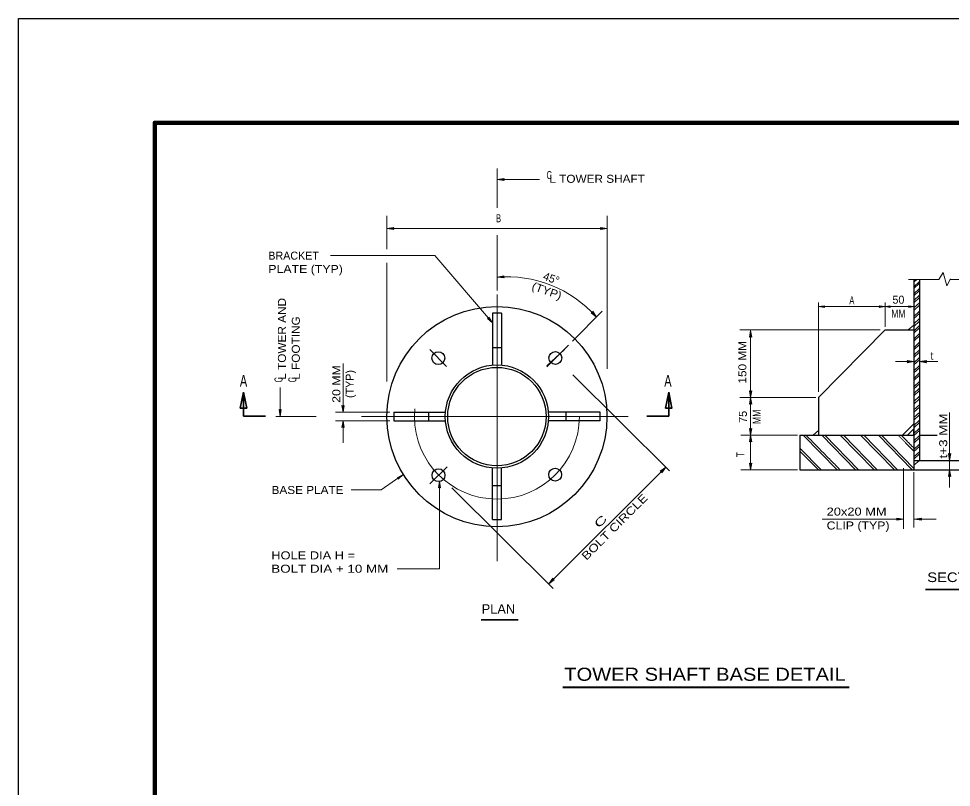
# Model space of a CAD drawing. Extents: x 312601.859 to 312602.7, y 144420.109 to 144420.704.
# Drawn here: x 312601.8593 to 312602.209, y 144420.4155 to 144420.7035 of the extents above; entities that cross this region are included whole.
import ezdxf
from ezdxf.enums import TextEntityAlignment as Align

# ---------------------------------------------------------------- set-up
doc = ezdxf.new("R2010")
doc.units = 0
doc.header["$LTSCALE"] = 0.0012
doc.linetypes.add('DOT_DASHED', pattern=[7.7, 5, -1.2, 0.3, -1.2])
doc.linetypes.add('LONG_DASHED', pattern=[7.5, 6, -1.5])
for name, color, linetype, lineweight in [('1', 7, 'Continuous', 13), ('2', 7, 'Continuous', 13), ('39', 7, 'Continuous', 13)]:
    doc.layers.add(name, color=color, linetype=linetype, lineweight=lineweight)

msp = doc.modelspace()

# ---------------------------------------------------------------- hatches: boundary and pattern name
at = {"layer": '39'}
for points in [[(312602.041, 144420.6432), (312602.0413, 144420.6428), (312602.0387, 144420.6432), (312602.0413, 144420.6436)], [(312601.9996, 144420.6249), (312601.9999, 144420.6245), (312601.9973, 144420.6249), (312601.9999, 144420.6253)], [(312602.0776, 144420.6249), (312602.0774, 144420.6253), (312602.0799, 144420.6249), (312602.0774, 144420.6245)], [(312602.041, 144420.6068), (312602.0413, 144420.6064), (312602.0387, 144420.6066), (312602.0412, 144420.6072)], [(312602.0743, 144420.5934), (312602.0745, 144420.5939), (312602.0759, 144420.5917), (312602.0739, 144420.5933)], [(312602.1612, 144420.5956), (312602.1614, 144420.5953), (312602.1592, 144420.5956), (312602.1614, 144420.5959)], [(312602.1821, 144420.5956), (312602.1819, 144420.5959), (312602.1841, 144420.5956), (312602.1819, 144420.5953)], [(312602.1858, 144420.5956), (312602.186, 144420.5953), (312602.1841, 144420.5956), (312602.186, 144420.5959)], [(312602.1932, 144420.5956), (312602.193, 144420.5959), (312602.1949, 144420.5956), (312602.193, 144420.5953)], [(312602.0354, 144420.5913), (312602.0355, 144420.5917), (312602.0369, 144420.5895), (312602.035, 144420.5912)], [(312602.1337, 144420.5843), (312602.1333, 144420.5841), (312602.1337, 144420.5866), (312602.1341, 144420.5841)], [(312602.1926, 144420.575), (312602.1924, 144420.5754), (312602.1949, 144420.575), (312602.1924, 144420.5746)], [(312602.1993, 144420.575), (312602.1996, 144420.5746), (312602.197, 144420.575), (312602.1996, 144420.5754)], [(312602.1337, 144420.5638), (312602.1341, 144420.5641), (312602.1337, 144420.5615), (312602.1333, 144420.5641)], [(312601.9809, 144420.5583), (312601.9813, 144420.5586), (312601.9809, 144420.556), (312601.9805, 144420.5586)], [(312602.1337, 144420.5592), (312602.1333, 144420.559), (312602.1337, 144420.5615), (312602.1341, 144420.559)], [(312601.9573, 144420.5567), (312601.9577, 144420.557), (312601.9573, 144420.5544), (312601.9569, 144420.557)], [(312601.9809, 144420.5505), (312601.9805, 144420.5503), (312601.9809, 144420.5528), (312601.9813, 144420.5503)], [(312602.1337, 144420.5497), (312602.1341, 144420.55), (312602.1337, 144420.5474), (312602.1333, 144420.55)], [(312602.1337, 144420.5451), (312602.1333, 144420.5449), (312602.1337, 144420.5474), (312602.1341, 144420.5449)], [(312602.2083, 144420.5403), (312602.2087, 144420.5406), (312602.2083, 144420.538), (312602.2079, 144420.5406)], [(312602.1003, 144420.5338), (312602.0998, 144420.5339), (312602.1019, 144420.5354), (312602.1004, 144420.5333)], [(312602.1337, 144420.5367), (312602.1341, 144420.537), (312602.1337, 144420.5344), (312602.1333, 144420.537)], [(312602.2083, 144420.5322), (312602.2079, 144420.532), (312602.2083, 144420.5345), (312602.2087, 144420.532)], [(312602.0016, 144420.5314), (312602.0012, 144420.5315), (312602.0035, 144420.5327), (312602.0016, 144420.5309)], [(312602.0171, 144420.5279), (312602.0167, 144420.5277), (312602.0171, 144420.5302), (312602.0175, 144420.5277)], [(312602.1887, 144420.516), (312602.1885, 144420.5164), (312602.191, 144420.516), (312602.1885, 144420.5156)], [(312602.1974, 144420.516), (312602.1977, 144420.5156), (312602.1951, 144420.516), (312602.1977, 144420.5164)], [(312602.0596, 144420.4933), (312602.0601, 144420.4932), (312602.058, 144420.4917), (312602.0595, 144420.4938)]]:
    msp.add_hatch(color=256, dxfattribs=at).paths.add_polyline_path(points)

# ---------------------------------------------------------------- linework, layer by layer
at = {"layer": '1'}
for p, q in [((312602.0387, 144420.6473), (312602.0387, 144420.6326)), ((312602.0387, 144420.6432), (312602.0545, 144420.6432)), ((312601.9973, 144420.6171), (312601.9973, 144420.6296)), ((312602.0799, 144420.5723), (312602.0799, 144420.6296)), ((312601.9973, 144420.6249), (312602.0799, 144420.6249)), ((312602.0387, 144420.6224), (312602.0387, 144420.6016)), ((312601.9762, 144420.6148), (312602.0153, 144420.6148)), ((312601.9973, 144420.5676), (312601.9973, 144420.612)), ((312602.1929, 144420.6058), (312602.2042, 144420.6058)), ((312602.1949, 144420.6048), (312602.196, 144420.6058)), ((312602.1949, 144420.6053), (312602.1954, 144420.6058)), ((312602.1949, 144420.603), (312602.197, 144420.605)), ((312602.1949, 144420.6024), (312602.197, 144420.6044)), ((312602.2085, 144420.6058), (312602.2239, 144420.6058)), ((312602.1949, 144420.6004), (312602.197, 144420.6024)), ((312602.1949, 144420.5997), (312602.197, 144420.6017)), ((312602.1592, 144420.5971), (312602.1592, 144420.5637)), ((312602.1841, 144420.588), (312602.1841, 144420.5971)), ((312602.1949, 144420.5979), (312602.197, 144420.5999)), ((312602.1949, 144420.597), (312602.197, 144420.599)), ((312602.1949, 144420.5951), (312602.197, 144420.597)), ((312602.1592, 144420.5956), (312602.1841, 144420.5956)), ((312602.1841, 144420.5956), (312602.1949, 144420.5956)), ((312602.1949, 144420.5942), (312602.197, 144420.5962)), ((312602.1949, 144420.5919), (312602.197, 144420.5939)), ((312602.1949, 144420.5911), (312602.197, 144420.593)), ((312602.1949, 144420.5891), (312602.197, 144420.5911)), ((312602.1949, 144420.5882), (312602.197, 144420.5902)), ((312602.1297, 144420.5869), (312602.1823, 144420.5869)), ((312602.1337, 144420.5615), (312602.1337, 144420.5866)), ((312602.1949, 144420.5864), (312602.197, 144420.5885)), ((312602.1949, 144420.5856), (312602.197, 144420.5876)), ((312602.1949, 144420.5834), (312602.197, 144420.5855)), ((312602.1949, 144420.5826), (312602.197, 144420.5846)), ((312602.0639, 144420.5796), (312602.0621, 144420.5778)), ((312602.1949, 144420.5794), (312602.197, 144420.5814)), ((312602.1949, 144420.5774), (312602.197, 144420.5794)), ((312602.197, 144420.5823), (312602.1951, 144420.5804)), ((312602.1949, 144420.5765), (312602.197, 144420.5785)), ((312602.1949, 144420.5746), (312602.197, 144420.5766)), ((312601.9809, 144420.5743), (312601.9809, 144420.556)), ((312602.188, 144420.575), (312602.1949, 144420.575)), ((312602.1949, 144420.5738), (312602.197, 144420.5757)), ((312602.1949, 144420.5716), (312602.197, 144420.5736)), ((312602.1949, 144420.5708), (312602.197, 144420.5727)), ((312602.197, 144420.575), (312602.2039, 144420.575)), ((312602.067, 144420.57), (312602.1033, 144420.5341)), ((312602.1949, 144420.5687), (312602.197, 144420.5708)), ((312602.1949, 144420.5679), (312602.197, 144420.5699)), ((312602.1949, 144420.5656), (312602.197, 144420.5676)), ((312602.1949, 144420.5648), (312602.197, 144420.5667)), ((312601.9573, 144420.5653), (312601.9573, 144420.5544)), ((312602.1949, 144420.563), (312602.197, 144420.565)), ((312602.1949, 144420.5622), (312602.197, 144420.5642)), ((312602.1949, 144420.56), (312602.197, 144420.562)), ((312602.1297, 144420.5615), (312602.1582, 144420.5615)), ((312602.1949, 144420.5591), (312602.197, 144420.5611)), ((312602.1949, 144420.5569), (312602.197, 144420.5588)), ((312601.9781, 144420.556), (312601.9985, 144420.556)), ((312602.1949, 144420.556), (312602.197, 144420.5579)), ((312602.1949, 144420.554), (312602.197, 144420.5559)), ((312602.1949, 144420.5531), (312602.197, 144420.5551)), ((312601.9708, 144420.5544), (312601.9557, 144420.5544)), ((312601.9781, 144420.5528), (312601.9985, 144420.5528)), ((312601.9809, 144420.5528), (312601.9809, 144420.5446)), ((312602.1949, 144420.5511), (312602.197, 144420.5531)), ((312602.1949, 144420.5502), (312602.197, 144420.5522)), ((312602.1947, 144420.5498), (312602.1947, 144420.5474)), ((312602.1949, 144420.5481), (312602.197, 144420.5501)), ((312602.1949, 144420.5473), (312602.197, 144420.5492)), ((312602.13, 144420.5474), (312602.1513, 144420.5474)), ((312602.1534, 144420.5474), (312602.1661, 144420.5345)), ((312602.1604, 144420.5474), (312602.173, 144420.5345)), ((312602.1615, 144420.5474), (312602.1742, 144420.5345)), ((312602.1673, 144420.5474), (312602.18, 144420.5345)), ((312602.1685, 144420.5474), (312602.1811, 144420.5345)), ((312602.1749, 144420.5474), (312602.1877, 144420.5345)), ((312602.1761, 144420.5474), (312602.1888, 144420.5345)), ((312602.1817, 144420.5474), (312602.1943, 144420.5345)), ((312602.1828, 144420.5474), (312602.1949, 144420.535)), ((312602.1949, 144420.5453), (312602.197, 144420.5473)), ((312602.1949, 144420.5444), (312602.197, 144420.5464)), ((312602.1522, 144420.5426), (312602.1602, 144420.5345)), ((312602.1522, 144420.5414), (312602.1591, 144420.5345)), ((312602.1949, 144420.5421), (312602.197, 144420.5441)), ((312602.1949, 144420.5413), (312602.197, 144420.5432)), ((312602.1949, 144420.5393), (312602.197, 144420.5412)), ((312602.1949, 144420.5384), (312602.197, 144420.5404)), ((312602.197, 144420.538), (312602.1949, 144420.5362)), ((312602.058, 144420.4917), (312602.1019, 144420.5354)), ((312602.13, 144420.5344), (312602.1513, 144420.5344)), ((312602.191, 144420.5123), (312602.191, 144420.5351)), ((312602.1949, 144420.5336), (312602.1949, 144420.5129)), ((312602.0171, 144420.5302), (312602.0171, 144420.4973)), ((312602.0217, 144420.5277), (312602.0597, 144420.49)), ((312601.9839, 144420.5269), (312601.9952, 144420.5269)), ((312602.1605, 144420.516), (312602.191, 144420.516)), ((312602.1951, 144420.516), (312602.2032, 144420.516)), ((312602.0171, 144420.4973), (312602.0012, 144420.4973))]:
    msp.add_line(p, q, dxfattribs=at)
at = {"layer": '1', "lineweight": 25}
for p, q in [((312602.1949, 144420.6058), (312602.1949, 144420.5345)), ((312602.197, 144420.6058), (312602.197, 144420.538)), ((312602.0369, 144420.5932), (312602.0369, 144420.5738)), ((312602.0403, 144420.5932), (312602.0369, 144420.5932)), ((312602.0403, 144420.5932), (312602.0403, 144420.5738)), ((312602.1592, 144420.5615), (312602.1841, 144420.5869)), ((312602.1841, 144420.5869), (312602.1949, 144420.5869)), ((312602.0403, 144420.5802), (312602.0369, 144420.5802)), ((312602.1592, 144420.5615), (312602.1592, 144420.5474)), ((312601.9999, 144420.556), (312601.9999, 144420.5528)), ((312601.9999, 144420.556), (312602.0193, 144420.556)), ((312602.0129, 144420.556), (312602.0129, 144420.5528)), ((312602.0773, 144420.556), (312602.0579, 144420.556)), ((312602.0645, 144420.5528), (312602.0645, 144420.556)), ((312602.0773, 144420.5528), (312602.0773, 144420.556)), ((312601.9999, 144420.5528), (312602.0193, 144420.5528)), ((312602.0773, 144420.5528), (312602.0579, 144420.5528)), ((312602.1906, 144420.5474), (312602.1949, 144420.5517)), ((312602.1522, 144420.5474), (312602.1522, 144420.5345)), ((312602.1949, 144420.538), (312602.2391, 144420.538)), ((312602.0369, 144420.5158), (312602.0369, 144420.535)), ((312602.0403, 144420.5158), (312602.0403, 144420.535)), ((312602.1522, 144420.5345), (312602.2818, 144420.5345)), ((312602.0369, 144420.5286), (312602.0403, 144420.5286)), ((312602.0369, 144420.5158), (312602.0403, 144420.5158))]:
    msp.add_line(p, q, dxfattribs=at)
at = {"layer": '1', "linetype": 'DOT_DASHED'}
for p, q in [((312602.0387, 144420.6002), (312602.0387, 144420.4942)), ((312602.0135, 144420.5796), (312602.0197, 144420.5732)), ((312602.0639, 144420.5796), (312602.0573, 144420.5734)), ((312602.0878, 144420.5544), (312601.972, 144420.5544)), ((312602.0135, 144420.5292), (312602.0199, 144420.5356))]:
    msp.add_line(p, q, dxfattribs=at)
at = {"layer": '1', "linetype": 'LONG_DASHED', "lineweight": 25}
msp.add_line((312602.197, 144420.5474), (312602.2036, 144420.5474), dxfattribs=at)
at = {"layer": '1'}
for points in [[(312602.1949, 144420.5869), (312602.1949, 144420.5887), (312602.1928, 144420.5869)], [(312602.1592, 144420.5474), (312602.1592, 144420.5492), (312602.1571, 144420.5474)], [(312602.1925, 144420.5474), (312602.1949, 144420.5498), (312602.1949, 144420.5474)], [(312602.1949, 144420.538), (312602.1949, 144420.5362), (312602.197, 144420.538)]]:
    msp.add_lwpolyline(points, close=True, dxfattribs=at)
for points in [[(312602.1337, 144420.5344), (312602.1337, 144420.5474), (312602.1337, 144420.5615)], [(312602.2083, 144420.5559), (312602.2083, 144420.538), (312602.2083, 144420.5345), (312602.2083, 144420.5278)], [(312602.1925, 144420.5474), (312602.1949, 144420.5498), (312602.1949, 144420.5474)]]:
    msp.add_lwpolyline(points, dxfattribs=at)
at = {"layer": '1', "lineweight": 25}
for centre, radius in [((312602.0386, 144420.5544), 0.04125), ((312602.01662, 144420.5763), 0.0024), ((312602.0605, 144420.57638), 0.0024), ((312602.0386, 144420.5544), 0.01935), ((312602.0386, 144420.5544), 0.01845), ((312602.0167, 144420.53243), 0.0024), ((312602.06042, 144420.53265), 0.0024)]:
    msp.add_circle(centre, radius, dxfattribs=at)
at = {"layer": '1', "linetype": 'DOT_DASHED'}
msp.add_circle((312602.0386, 144420.5544), 0.0309, dxfattribs=at)
at = {"layer": '1', "lineweight": 25}
msp.add_open_spline([(312602.1522, 144420.5474), (312602.1949, 144420.5474)], degree=1, dxfattribs=at)
at = {"layer": '1'}
for points in [[(312602.1545, 144420.5474), (312602.1672, 144420.5345)], [(312602.189, 144420.5474), (312602.1949, 144420.5414)], [(312602.1902, 144420.5474), (312602.1949, 144420.5426)]]:
    msp.add_open_spline(points, degree=1, dxfattribs=at)
at = {"layer": '2'}
for p, q in [((312602.0369, 144420.5895), (312602.0153, 144420.6148)), ((312602.0669, 144420.5827), (312602.0781, 144420.5939)), ((312601.9952, 144420.5269), (312602.0035, 144420.5327))]:
    msp.add_line(p, q, dxfattribs=at)
at = {"layer": '2', "linetype": 'DOT_DASHED'}
msp.add_line((312602.0573, 144420.5731), (312602.0654, 144420.5812), dxfattribs=at)
at = {"layer": '2', "lineweight": 35}
for p, q in [((312602.2352, 144420.4896), (312602.1993, 144420.4896)), ((312602.0466, 144420.4782), (312602.0327, 144420.4782))]:
    msp.add_line(p, q, dxfattribs=at)
at = {"layer": '2', "lineweight": 40}
msp.add_line((312602.1707, 144420.4529), (312602.0633, 144420.4529), dxfattribs=at)
at = {"layer": '2'}
msp.add_lwpolyline([(312602.2042, 144420.6058), (312602.2059, 144420.6084), (312602.2073, 144420.6034), (312602.2086, 144420.606)], dxfattribs=at)
msp.add_ellipse((312602.04346, 144420.55817), major_axis=(-0.00491, 0.04837), ratio=0.934119, start_param=5.379709, end_param=6.279803, dxfattribs=at)
at = {"layer": '39', "lineweight": 25}
for p, q in [((312601.8593, 144420.7035), (312602.7003, 144420.7035)), ((312601.8593, 144420.1095), (312601.8593, 144420.7035))]:
    msp.add_line(p, q, dxfattribs=at)
at = {"layer": '39', "lineweight": 158}
msp.add_lwpolyline([(312601.9103, 144420.1247), (312601.9103, 144420.6645), (312602.6853, 144420.6645)], dxfattribs=at)
at = {"layer": '39'}
for points in [[(312602.041, 144420.6432), (312602.0413, 144420.6428), (312602.0387, 144420.6432), (312602.0413, 144420.6436)], [(312601.9996, 144420.6249), (312601.9999, 144420.6245), (312601.9973, 144420.6249), (312601.9999, 144420.6253)], [(312602.0776, 144420.6249), (312602.0774, 144420.6253), (312602.0799, 144420.6249), (312602.0774, 144420.6245)], [(312602.041, 144420.6068), (312602.0413, 144420.6064), (312602.0387, 144420.6066), (312602.0412, 144420.6072)], [(312602.0743, 144420.5934), (312602.0745, 144420.5939), (312602.0759, 144420.5917), (312602.0739, 144420.5933)], [(312602.1612, 144420.5956), (312602.1614, 144420.5953), (312602.1592, 144420.5956), (312602.1614, 144420.5959)], [(312602.1821, 144420.5956), (312602.1819, 144420.5959), (312602.1841, 144420.5956), (312602.1819, 144420.5953)], [(312602.1858, 144420.5956), (312602.186, 144420.5953), (312602.1841, 144420.5956), (312602.186, 144420.5959)], [(312602.1932, 144420.5956), (312602.193, 144420.5959), (312602.1949, 144420.5956), (312602.193, 144420.5953)], [(312602.0354, 144420.5913), (312602.0355, 144420.5917), (312602.0369, 144420.5895), (312602.035, 144420.5912)], [(312602.1337, 144420.5843), (312602.1333, 144420.5841), (312602.1337, 144420.5866), (312602.1341, 144420.5841)], [(312602.1926, 144420.575), (312602.1924, 144420.5754), (312602.1949, 144420.575), (312602.1924, 144420.5746)], [(312602.1993, 144420.575), (312602.1996, 144420.5746), (312602.197, 144420.575), (312602.1996, 144420.5754)], [(312601.9448, 144420.5576), (312601.9436, 144420.5636), (312601.9424, 144420.5576)], [(312602.1018, 144420.5576), (312602.103, 144420.5636), (312602.1042, 144420.5576)], [(312602.1337, 144420.5638), (312602.1341, 144420.5641), (312602.1337, 144420.5615), (312602.1333, 144420.5641)], [(312601.9809, 144420.5583), (312601.9813, 144420.5586), (312601.9809, 144420.556), (312601.9805, 144420.5586)], [(312602.1337, 144420.5592), (312602.1333, 144420.559), (312602.1337, 144420.5615), (312602.1341, 144420.559)], [(312601.9573, 144420.5567), (312601.9577, 144420.557), (312601.9573, 144420.5544), (312601.9569, 144420.557)], [(312601.9809, 144420.5505), (312601.9805, 144420.5503), (312601.9809, 144420.5528), (312601.9813, 144420.5503)], [(312602.1337, 144420.5497), (312602.1341, 144420.55), (312602.1337, 144420.5474), (312602.1333, 144420.55)], [(312602.1337, 144420.5451), (312602.1333, 144420.5449), (312602.1337, 144420.5474), (312602.1341, 144420.5449)], [(312602.2083, 144420.5403), (312602.2087, 144420.5406), (312602.2083, 144420.538), (312602.2079, 144420.5406)], [(312602.1003, 144420.5338), (312602.0998, 144420.5339), (312602.1019, 144420.5354), (312602.1004, 144420.5333)], [(312602.1337, 144420.5367), (312602.1341, 144420.537), (312602.1337, 144420.5344), (312602.1333, 144420.537)], [(312602.2083, 144420.5322), (312602.2079, 144420.532), (312602.2083, 144420.5345), (312602.2087, 144420.532)], [(312602.0016, 144420.5314), (312602.0012, 144420.5315), (312602.0035, 144420.5327), (312602.0016, 144420.5309)], [(312602.0171, 144420.5279), (312602.0167, 144420.5277), (312602.0171, 144420.5302), (312602.0175, 144420.5277)], [(312602.1887, 144420.516), (312602.1885, 144420.5164), (312602.191, 144420.516), (312602.1885, 144420.5156)], [(312602.1974, 144420.516), (312602.1977, 144420.5156), (312602.1951, 144420.516), (312602.1977, 144420.5164)], [(312602.0596, 144420.4933), (312602.0601, 144420.4932), (312602.058, 144420.4917), (312602.0595, 144420.4938)]]:
    msp.add_lwpolyline(points, close=True, dxfattribs=at)
at = {"layer": '39', "lineweight": 35}
for points in [[(312601.9436, 144420.5636), (312601.9424, 144420.5576), (312601.9448, 144420.5576)], [(312602.103, 144420.5636), (312602.1042, 144420.5576), (312602.1018, 144420.5576)]]:
    msp.add_lwpolyline(points, close=True, dxfattribs=at)
for points in [[(312601.9436, 144420.5633), (312601.9436, 144420.5546), (312601.9518, 144420.5546)], [(312602.103, 144420.5633), (312602.103, 144420.5546), (312602.0948, 144420.5546)]]:
    msp.add_lwpolyline(points, dxfattribs=at)

# ---------------------------------------------------------------- texts
at = {"layer": '2'}
for s, height, width, p in [('C', 0.003, 0.6, (312602.0582, 144420.6434)), ('L TOWER SHAFT', 0.003, 1.1, (312602.07615, 144420.642)), ('B', 0.003, 0.7, (312602.0392, 144420.6272)), ('A', 0.003, 0.7, (312602.17165, 144420.5965)), ('MM', 0.003, 0.8, (312602.1891, 144420.5915)), ('A', 0.0044, 0.7, (312601.9436, 144420.5656)), ('A', 0.0044, 0.7, (312602.1027, 144420.5656)), ('BASE PLATE', 0.003, 1.1, (312601.9676, 144420.5254)), ('SECTION A-A', 0.0036, 1.15, (312602.2176, 144420.4924)), ('TOWER SHAFT BASE DETAIL', 0.0049, 1.15, (312602.1166, 144420.4554))]:
    msp.add_text(s, height=height, dxfattribs=dict(at, width=width)).set_placement(p, align=Align.CENTER)
msp.add_text('BRACKET', height=0.003, dxfattribs=at).set_placement((312601.9529, 144420.6132))
for s, width, p in [('PLATE (TYP)', 1.15, (312601.9529, 144420.6082)), ('20x20 MM', 1.2, (312602.1622, 144420.5173)), ('CLIP (TYP)', 1.15, (312602.1622, 144420.5121)), ('HOLE DIA H =', 1.2, (312601.954, 144420.5009)), ('BOLT DIA + 10 MM', 1.25, (312601.954, 144420.4959))]:
    msp.add_text(s, height=0.003, dxfattribs=dict(at, width=width)).set_placement(p)
for s, rotation, p in [('45°', 340.204, (312602.05849, 144420.60478)), ('(TYP)', 90, (312601.9849, 144420.5666)), ('75', 90, (312602.1323, 144420.5543))]:
    msp.add_text(s, height=0.003, rotation=rotation, dxfattribs=at).set_placement(p, align=Align.CENTER)
for s, rotation, width, p in [('(TYP)', 340.204, 1.1, (312602.05679, 144420.60012)), ('150 MM', 90, 1.1, (312602.1321, 144420.57475)), ('20 MM', 90, 1.15, (312601.9799, 144420.5666)), ('C', 90, 0.6, (312601.9582, 144420.5682)), ('C', 90, 0.6, (312601.9634, 144420.5682)), ('MM', 90, 0.8, (312602.1375, 144420.5543)), ('t+3 MM', 90, 1.25, (312602.2074, 144420.54715)), ('T', 90, 0.8, (312602.1314, 144420.54015)), ('BOLT CIRCLE', 45, 1.25, (312602.08379, 144420.51199)), ('C', 45, 1.65, (312602.07849, 144420.51409))]:
    msp.add_text(s, height=0.003, rotation=rotation, dxfattribs=dict(at, width=width)).set_placement(p, align=Align.CENTER)
at = {"layer": '2', "width": 1.1}
for s, p in [('L TOWER AND', (312601.9595, 144420.5682)), ('L FOOTING', (312601.9647, 144420.5682))]:
    msp.add_text(s, height=0.003, rotation=90, dxfattribs=at).set_placement(p)
at = {"layer": '2'}
for s, height, p in [('50', 0.003, (312602.1891, 144420.5967)), ('t', 0.003, (312602.20165, 144420.5757)), ('PLAN', 0.0036, (312602.03915, 144420.4805))]:
    msp.add_text(s, height=height, dxfattribs=at).set_placement(p, align=Align.CENTER)

doc.saveas('drawing.dxf')
